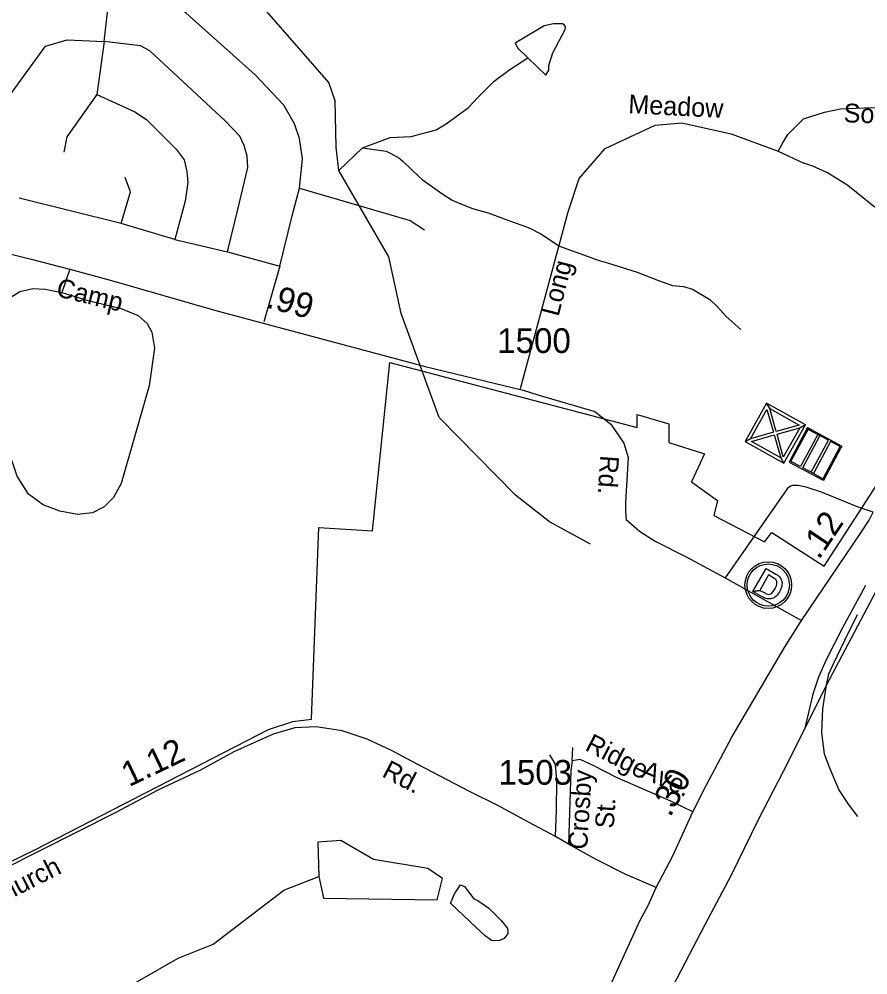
# Model space of a CAD drawing. Extents: x 1473865 to 1648260, y 639067 to 773536.
# Drawn here: x 1540456 to 1544745, y 681829 to 686657 of the extents above; entities that cross this region are included whole.
import ezdxf

# ---------------------------------------------------------------- set-up
doc = ezdxf.new("R2010")
doc.units = 0
for name, color, linetype in [('Exist Boundary Political City Limit New', 7, 'Continuous'), ('Exist Civil Correctional or Penal Institution CELL', 7, 'Continuous'), ('Exist Civil NCDOT Division Office Label', 7, 'Continuous'), ('Exist Civil NCDOT Garage or Maintenance Office CELL', 7, 'Continuous'), ('Exist Hydrographic Creek Single Shore', 7, 'Continuous'), ('Exist Hydrographic Misc Water Feature', 7, 'Continuous'), ('Exist Hydrographic Pond Under 1500 Sq Ft', 7, 'Continuous'), ('Exist Railroad Mainline', 7, 'Continuous'), ('Exist Railroad Siding', 7, 'Continuous'), ('Exist Road Non-System Type 51', 7, 'Continuous'), ('Exist Road Non-System Type 51 Label', 7, 'Continuous'), ('Exist Road Primary US Mileage Hundredths English Label', 7, 'Continuous'), ('Exist Road Primary US UnDivided 4 Lane Attributed', 7, 'Continuous'), ('Exist Road Secondary Mileage Hundredths English Label', 7, 'Continuous'), ('Exist Road Secondary Type 51 Attributed', 7, 'Continuous'), ('Exist Road Secondary Type 51 Label', 7, 'Continuous'), ('Exist Road Secondary Type 51 Number Label', 7, 'Continuous'), ('Map Preparation Boundary City Limit Buffer Line', 7, 'Continuous')]:
    doc.layers.add(name, color=color, linetype=linetype)

msp = doc.modelspace()

# ---------------------------------------------------------------- linework, layer by layer
at = {"layer": 'Exist Boundary Political City Limit New'}
msp.add_lwpolyline([(1539344, 681881.7), (1540535.4, 682460.9), (1541716.6, 683068.1), (1541838.6, 683108.7), (1541933.5, 683120.4), (1541970, 684088.7), (1542241.9, 684072.6), (1542329, 684922.1), (1543579.2, 684593.6), (1543579.2, 684659.9), (1543740, 684612.6), (1543740, 684517.9), (1543919.6, 684461.2), (1543853.5, 684319.2), (1543985.9, 684224.6), (1543967, 684148.9), (1544222.2, 684016.4), (1544260, 684063.8), (1544524.8, 683893.4), (1545174, 684896.9)], dxfattribs=at)
at = {"layer": 'Exist Civil Correctional or Penal Institution CELL'}
msp.add_lwpolyline([(1544521, 684326.7), (1544515.2, 684329.8), (1544605.2, 684497.5), (1544557, 684523.4), (1544470.1, 684361.5), (1544416.1, 684390.4), (1544503, 684552.4), (1544491.5, 684558.6), (1544404.6, 684396.6), (1544356.4, 684422.5), (1544443.3, 684584.4), (1544440.6, 684593.4), (1544347.4, 684419.8), (1544515.2, 684329.8), (1544518.3, 684335.6), (1544470.1, 684361.5), (1544458.6, 684367.7), (1544545.5, 684529.6), (1544443.3, 684584.4), (1544440.6, 684593.4), (1544614.2, 684500.2), (1544611, 684494.4)], close=True, dxfattribs=at)
at = {"layer": 'Exist Civil NCDOT Division Office Label'}
msp.add_lwpolyline([(1544231.5, 683882.5), (1544280.3, 683854.1), (1544289.6, 683847.7), (1544298.5, 683839.4), (1544301.4, 683835.6), (1544304.5, 683831.1), (1544306, 683828.5), (1544307.7, 683824.5), (1544310.3, 683817.7), (1544311.1, 683812.7), (1544311.5, 683808.8), (1544311.7, 683805.9), (1544311, 683798.7), (1544310.2, 683792.9), (1544308.6, 683787.1), (1544307, 683782.1), (1544305.9, 683779.2), (1544302.3, 683771.5), (1544300.2, 683767.1), (1544298.9, 683764.8), (1544293.9, 683757.2), (1544290.3, 683751.9), (1544286, 683747), (1544281, 683741.7), (1544275.5, 683737.5), (1544271.1, 683734.4), (1544264.8, 683731.4), (1544260.5, 683729.8), (1544255.1, 683728.7), (1544249.1, 683727.9), (1544242.1, 683728.1), (1544236.8, 683728.8), (1544229.6, 683730.7), (1544224, 683732.6), (1544215.7, 683736.5), (1544210.8, 683739.2), (1544164.6, 683765.5), (1544199.3, 683771.6), (1544220.7, 683760.1), (1544233.7, 683753.8), (1544241.2, 683751.3), (1544248.5, 683752.1), (1544254.7, 683754.7), (1544259.6, 683757.7), (1544267.2, 683765.2), (1544276.8, 683780.9), (1544281.4, 683790.2), (1544283.4, 683795.5), (1544285.1, 683803.5), (1544285.6, 683810.1), (1544284.4, 683816.2), (1544283.5, 683820.3), (1544280, 683826.2), (1544275.7, 683830.5), (1544242.8, 683849.2), (1544199.3, 683771.6), (1544164.6, 683765.5), (1544199.3, 683771.6), (1544164.6, 683765.5)], close=True, dxfattribs=at)
for radius in [118.2, 106.9]:
    msp.add_circle((1544241.8, 683798.2), radius, dxfattribs=at)
at = {"layer": 'Exist Civil NCDOT Garage or Maintenance Office CELL'}
msp.add_lwpolyline([(1544124.4, 684524), (1544321.2, 684413.7), (1544305.5, 684440.4), (1544156.6, 684523.9), (1544271.8, 684556.4), (1544305.5, 684440.4), (1544321.2, 684413.7), (1544429.5, 684607), (1544401.3, 684592.8), (1544317.8, 684443.9), (1544286.1, 684560.4), (1544401.3, 684592.8), (1544429.5, 684607), (1544232.7, 684717.3), (1544249.6, 684689.8), (1544398.5, 684606.4), (1544282.1, 684574.6), (1544249.6, 684689.8), (1544232.7, 684717.3), (1544124.4, 684524), (1544151.9, 684536.9), (1544235.3, 684685.8), (1544267.8, 684570.6), (1544151.9, 684536.9)], close=True, dxfattribs=at)
at = {"layer": 'Exist Hydrographic Creek Single Shore'}
msp.add_lwpolyline([(1537169.4, 683128.3), (1537426.4, 683057.5), (1537533.3, 682963.4), (1537797.3, 682826.8), (1538011.4, 682605.9), (1538176.4, 682536.9), (1538455.3, 682232.6), (1538819.4, 682025), (1538867.4, 681941.9), (1538862.4, 681590.8), (1538894.4, 681498.2), (1538967.4, 681404.8), (1539033.4, 681370.7), (1539242.3, 681353.4), (1540486.4, 681508.8), (1540679.4, 681580.4), (1541259.4, 681913.3), (1541436.4, 681985.2), (1541794.2, 682257.3), (1541971.2, 682326)], dxfattribs=at)
at = {"layer": 'Exist Hydrographic Misc Water Feature'}
for points in [[(1542058.3, 686009.4), (1542053.5, 686243.3), (1542021.5, 686335.9), (1541357.4, 687097.6), (1541118.5, 687240.4), (1540701.5, 687216), (1540252.4, 687297.3), (1539812.5, 687411.1), (1539382.5, 687626.6), (1538992.3, 687804.1)], [(1543026.9, 686460.7), (1543118.6, 686374.3), (1543132.2, 686398.2), (1543132.6, 686422.2), (1543153.8, 686485.7), (1543216.1, 686604.3), (1543216.4, 686620.3), (1543210.6, 686628.5), (1543202.7, 686632.6), (1543156.7, 686633.6), (1543108.5, 686622.5), (1542962.7, 686534.5), (1542976.2, 686509.3), (1543026.9, 686460.7)], [(1542072.5, 685891.7), (1542191.9, 686007.4), (1542331.8, 686059.3), (1542437.4, 686064.4), (1542564.2, 686097.9), (1542613.3, 686128.2), (1542727.5, 686209.6), (1542773.4, 686261.5), (1542857, 686343.8), (1542936.1, 686402.2), (1543026.9, 686460.7)], [(1543343.5, 684004.9), (1543136.5, 684117.4), (1542964.4, 684252.1), (1542578.4, 684644), (1542386.5, 685169.8), (1542324.5, 685456.6), (1542072.5, 685891.7), (1542058.3, 686009.4)], [(1542191.9, 686007.4), (1542311.4, 685990.3), (1542373, 685957), (1542396.7, 685936.8), (1542477.4, 685859.7), (1542493.2, 685847.1), (1542592.3, 685775.3), (1542643.7, 685742.3), (1542699.5, 685718.2), (1542747.1, 685700.8), (1542826.6, 685677.9), (1542958.1, 685630.1), (1543005.9, 685612.7), (1543037.6, 685600.6), (1543093.3, 685571.5), (1543186.2, 685509.8), (1543387.3, 685436.8), (1543434.9, 685424.3), (1543578.5, 685377.9), (1543687.8, 685336.4), (1543757.5, 685311.1), (1543813.3, 685305.9), (1543859.3, 685293.5), (1543946.3, 685240), (1543985.8, 685203.1), (1544029, 685154.7), (1544103.9, 685089.2)], [(1542660.6, 682245.3), (1542662.6, 682248.5), (1542687.3, 682284.2), (1542707.1, 682276.4), (1542726.6, 682248.1), (1542754.3, 682213), (1542773.9, 682205.3), (1542829.4, 682166.4), (1542892.6, 682103.6), (1542922, 682066.8), (1542925.8, 682054.5), (1542925.5, 682038.9), (1542907.1, 682013), (1542882.9, 682003.6), (1542858.8, 682001.7), (1542842.9, 682003.6), (1542811.2, 682026.5), (1542763.9, 682070.9), (1542639.6, 682187.5), (1542635.8, 682191.6), (1542642.1, 682207.1), (1542656.4, 682238.8), (1542660.6, 682245.3)]]:
    msp.add_lwpolyline(points, dxfattribs=at)
at = {"layer": 'Exist Hydrographic Pond Under 1500 Sq Ft'}
msp.add_lwpolyline([(1541971.2, 682326), (1541994.2, 682217.2), (1542569.2, 682208.9), (1542596.2, 682316.6), (1542522.2, 682367.4), (1542247.2, 682412.3), (1542082.2, 682507.6), (1541965.2, 682500.1), (1541971.2, 682326)], dxfattribs=at)
at = {"layer": 'Exist Railroad Mainline'}
msp.add_line((1544424.5, 683068.3), (1544536.3, 683292.4), dxfattribs=at)
for points in [[(1544536.3, 683292.4), (1544803.2, 683799.5), (1544957.1, 684097.8), (1545129.8, 684395.6), (1545300.6, 684666.4), (1545425.9, 684856.2), (1545530.2, 684986.4)], [(1542691.3, 679713.8), (1542776.1, 679866.2), (1542960.2, 680222.3), (1543107.7, 680522.2), (1543265, 680833.4), (1543446.7, 681162.1), (1543596, 681459.4), (1543761.8, 681773.8), (1543923, 682083.6), (1544055.5, 682335), (1544190.3, 682610.6), (1544318.8, 682858.4), (1544424.5, 683068.3)]]:
    msp.add_lwpolyline(points, dxfattribs=at)
at = {"layer": 'Exist Railroad Siding'}
for points in [[(1544733.3, 683796.7), (1544617.6, 683582.9), (1544534.7, 683420.3), (1544495.1, 683333), (1544467.5, 683247.5), (1544452.4, 683183.8), (1544424.5, 683068.3)], [(1544536.3, 683292.4), (1544547.4, 683350.2), (1544570.2, 683397.8), (1544628.3, 683520.6), (1544692.6, 683649.4)], [(1544694.6, 682629.5), (1544647.8, 682692.4), (1544599.1, 682765.3), (1544553, 682874), (1544526.2, 682944.6), (1544512, 683052.8), (1544518.2, 683172.7), (1544536.3, 683292.4)]]:
    msp.add_lwpolyline(points, dxfattribs=at)
at = {"layer": 'Exist Road Non-System Type 51'}
for p, q in [((1540886, 686542.9), (1540915.8, 686816.8)), ((1540886, 686542.9), (1540848.6, 686276.4)), ((1540971.8, 685625.3), (1540456.7, 685752.3)), ((1541243.1, 685543.1), (1540971.8, 685625.3)), ((1541243.1, 685543.1), (1541509.4, 685480.8)), ((1541509.4, 685480.8), (1541773.2, 685408.6)), ((1541773.2, 685408.6), (1541692.4, 685128.5)), ((1540712.6, 685393.3), (1540672.2, 685276.1)), ((1543251.6, 682911.3), (1543254.9, 682977.3))]:
    msp.add_line(p, q, dxfattribs=at)
for points in [[(1541872.8, 685802.1), (1541887.7, 685951.5), (1541872.8, 686053.6), (1541847.9, 686128.3), (1541793.2, 686222.9), (1541648.8, 686374.8), (1541300.4, 686686), (1541209.5, 686762), (1541169.7, 686784.4), (1540915.8, 686816.8)], [(1540310.6, 686139.3), (1540589.8, 686520.4), (1540699.3, 686552.8), (1540886, 686542.9)], [(1541509.4, 685480.8), (1541561.7, 685695), (1541611.5, 685906.6), (1541609, 685963.9), (1541594, 686018.7), (1541571.6, 686066), (1541497, 686143.2), (1541116.2, 686496.8), (1541068.9, 686521.7), (1540886, 686542.9)], [(1540848.6, 686276.4), (1540696.8, 686062.3), (1540681.9, 685985.1)], [(1540848.6, 686276.4), (1541040.3, 686189.3), (1541100, 686149.4), (1541249.3, 686000), (1541290.4, 685946.5), (1541302.9, 685886.7), (1541307.8, 685831.9), (1541295.4, 685737.3), (1541243.1, 685543.1)], [(1544292.6, 685990.2), (1544314.6, 686031.5), (1544339.9, 686073.7), (1544419.9, 686152.3), (1544526.3, 686186), (1544606.4, 686202.9), (1544764.7, 686210.2), (1545019.9, 686194.4), (1545183.5, 686201), (1545278.4, 686217.2), (1545340.9, 686224.1), (1545419.6, 686258.9), (1545558.4, 686298.2)], [(1542989.9, 684791.8), (1543230.4, 685682.8), (1543285.5, 685852.5), (1543417.3, 686003.2), (1543670.8, 686121.2), (1543805.2, 686132.9), (1544054.1, 686078), (1544292.6, 685990.2), (1544422.2, 685930)], [(1545492.2, 685277.3), (1545281.7, 685381.3), (1545184.7, 685440.4), (1545069.5, 685526.2), (1545018.2, 685555.7), (1544948.5, 685609.3), (1544868.3, 685652.9), (1544776, 685709.7), (1544644.3, 685816.5), (1544540.7, 685881.2), (1544466.3, 685913.5), (1544422.2, 685930)], [(1540971.8, 685625.3), (1541019.1, 685784.6), (1540991.8, 685856.8)], [(1541773.2, 685408.6), (1541835.5, 685662.6), (1541872.8, 685802.1)], [(1541872.8, 685802.1), (1542432.8, 685640.2), (1542505, 685592.9)], [(1540218.2, 684740.8), (1540223.5, 684802.7), (1540222.2, 684946.8), (1540233.5, 685020.4), (1540279.4, 685113.5), (1540338.8, 685192.4), (1540413.9, 685252.9), (1540460.4, 685280.2), (1540524.6, 685296.9), (1540588.2, 685293.4), (1540672.2, 685276.1)], [(1540672.2, 685276.1), (1540803.5, 685235.6), (1540966.8, 685196.5), (1541058.3, 685160.6), (1541103.3, 685119.9), (1541126.4, 685075.4), (1541141, 684995.1), (1541113.3, 684803.8), (1540972.1, 684310.6), (1540932.9, 684241.3), (1540885.9, 684194.2), (1540827.3, 684163.4), (1540751.2, 684154.7), (1540662.1, 684171.1), (1540578.2, 684204.1), (1540503.2, 684257.4), (1540446.8, 684348.6), (1540401.5, 684483.4), (1540357.1, 684574.3), (1540268.9, 684665.9), (1540218.2, 684740.8)], [(1544771.8, 684166.1), (1544695.5, 684191.6), (1544510.9, 684267), (1544433.4, 684292.6), (1544393.6, 684301.4), (1544363.6, 684301.8), (1544350.8, 684296), (1544337.2, 684284.3), (1544024.1, 683834.1)], [(1543166.7, 682528.3), (1543170.9, 682661), (1543173.7, 682808.8), (1543167.1, 682893), (1543138.1, 682941.6)], [(1543251.6, 682911.3), (1543244.5, 682861.4), (1543233.1, 682489.3)], [(1543861, 682652.9), (1543749.7, 682706), (1543477.9, 682825.1), (1543357.1, 682887.4), (1543291.7, 682916.5), (1543251.6, 682911.3)]]:
    msp.add_lwpolyline(points, dxfattribs=at)
at = {"layer": 'Exist Road Primary US UnDivided 4 Lane Attributed'}
for points in [[(1544410.1, 683619.5), (1544705.4, 684056.6), (1544752.1, 684126.8), (1544771.8, 684166.1)], [(1543675.8, 682270.4), (1543758.9, 682430.8), (1543861, 682652.9), (1543927.5, 682785.6), (1544060.2, 683033.1), (1544324.6, 683483.7), (1544410.1, 683619.5)], [(1542123.7, 679050.4), (1542301.8, 679381.3), (1542372.4, 679516), (1542477.9, 679705.7), (1542911, 680613.4), (1543079.6, 680987.8), (1543109.2, 681055.5), (1543137.9, 681119.1), (1543178.1, 681208.1), (1543365.5, 681606.6), (1543463.7, 681818.4), (1543594.9, 682106), (1543634.2, 682179.2), (1543675.8, 682270.4)]]:
    msp.add_lwpolyline(points, dxfattribs=at)
at = {"layer": 'Exist Road Secondary Type 51 Attributed'}
for points in [[(1539910.1, 685572.4), (1539944.1, 685575.9), (1540042.2, 685556), (1540227.1, 685516.6), (1540517.6, 685445.1), (1540712.6, 685393.3), (1540923.6, 685337.4), (1541450.4, 685185), (1542508.8, 684902.8), (1543003, 684782.4), (1543077.2, 684758.9), (1543365.4, 684675.1), (1543445.8, 684610.7), (1543511.9, 684514.2), (1543533.4, 684442.6), (1543520.7, 684214.6), (1543520.7, 684171.6), (1543522.9, 684129.7), (1543590.6, 684070.7), (1543671, 684020.6), (1543826.3, 683941), (1544024.1, 683834.1), (1544410.1, 683619.5)], [(1543675.8, 682270.4), (1543519.1, 682337.5), (1543368.9, 682414.1), (1543233.1, 682489.3), (1543166.7, 682528.3), (1543029.4, 682600.6), (1542875.8, 682685.4), (1542732.8, 682755.6), (1542471.1, 682891.7), (1542340.5, 682960.2), (1542215.7, 683020.2), (1542088.6, 683062.1), (1541956.6, 683082.5), (1541849.2, 683076.7), (1541740.5, 683044.6), (1541540.8, 682956.4), (1541373.3, 682863.8), (1541157.3, 682761.9), (1540941.1, 682648), (1539991.2, 682170.1)]]:
    msp.add_lwpolyline(points, dxfattribs=at)
at = {"layer": 'Map Preparation Boundary City Limit Buffer Line'}
msp.add_lwpolyline([(1539344, 681881.7), (1540535.4, 682460.9), (1541716.6, 683068.1), (1541838.6, 683108.7), (1541933.5, 683120.4), (1541970, 684088.7), (1542241.9, 684072.6), (1542329, 684922.1), (1543579.2, 684593.6), (1543579.2, 684659.9), (1543740, 684612.6), (1543740, 684517.9), (1543919.6, 684461.2), (1543853.5, 684319.2), (1543985.9, 684224.6), (1543967, 684148.9), (1544222.2, 684016.4), (1544260, 684063.8), (1544524.8, 683893.4), (1545174, 684896.9)], dxfattribs=at)

# ---------------------------------------------------------------- texts
at = {"layer": 'Exist Road Non-System Type 51 Label'}
for s, rotation, p in [('Meadow', 357.113, (1543533, 686181.8)), ('Southmark', 358.2009, (1544621.6, 686135.8)), ('Long', 75.483, (1543181.5, 685150.9)), ('Ridge', 332.7322, (1543310.6, 682966.7)), ('Ave.', 336.3248, (1543592.6, 682828.5)), ('Crosby', 86.4225, (1543326.3, 682460.2)), ('St.', 86.4225, (1543460.8, 682566.5))]:
    msp.add_text(s, height=95, rotation=rotation, dxfattribs=at).set_placement(p)
at = {"layer": 'Exist Road Primary US Mileage Hundredths English Label'}
for s, rotation, p in [('.12', 56.0414, (1544497.4, 683922.5)), ('.30', 61.8037, (1543746.5, 682621.7))]:
    msp.add_text(s, height=125, rotation=rotation, dxfattribs=at).set_placement(p)
at = {"layer": 'Exist Road Secondary Mileage Hundredths English Label'}
for s, rotation, p in [('.99', 345.0571, (1541699.7, 685201.3)), ('1.12', 25.576, (1541011.4, 682776.8))]:
    msp.add_text(s, height=125, rotation=rotation, dxfattribs=at).set_placement(p)
at = {"layer": 'Exist Road Secondary Type 51 Label'}
for s, rotation, p in [('Camp', 346.3912, (1540638.3, 685258.2)), ('Rd.', 266.0913, (1543393.5, 684455.5)), ('Rd.', 332.3482, (1542284.4, 682833.6)), ('Church', 26.792, (1540311.2, 682160.8))]:
    msp.add_text(s, height=95, rotation=rotation, dxfattribs=at).set_placement(p)
at = {"layer": 'Exist Road Secondary Type 51 Number Label'}
for s, p in [('1500', (1542872.2, 684970.4)), ('1503', (1542878.4, 682789.9))]:
    msp.add_text(s, height=125, dxfattribs=at).set_placement(p)

doc.saveas('drawing.dxf')
